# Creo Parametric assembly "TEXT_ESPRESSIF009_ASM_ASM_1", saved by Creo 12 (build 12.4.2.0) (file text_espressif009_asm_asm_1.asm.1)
Units: Custom; MM, KILOGRAM, SECS

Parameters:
  PTC_WM_ITERATION = "0"
  PTC_WM_VERSION = "-.0"
  PTC_WM_LIFECYCLE_STATE = "In Work"
  PTC_WM_LIFECYCLE = "MO_CADDocument"
  PTC_WM_CREATED_BY = "Maximilian Roepper (Z0017RMS: MO)"
  PTC_WM_CREATED_ON = "18-Sep-26 11:36:42 AM"
  PTC_WM_MODIFIED_BY = "Maximilian Roepper (Z0017RMS: MO)"
  PTC_WM_MODIFIED_ON = "18-Sep-26 11:36:46 AM"
  PDMLINKNUMBER = "PDM000071455100"
  PTC_WM_NUMBER = "PDM000071455100"

Other parameters: WEIGHT, WEIGHT_FACTOR, WEIGHT_ADD, MC_ERRORS, SUPPLIER

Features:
  1. coordinate system
  2. imported feature
  3. component "TEXT_ESPRESSIF_PRT_1"
  4. component "TEXT_ESPRESSIF001_PRT_1"
  5. component "TEXT_ESPRESSIF002_PRT_1"
  6. component "TEXT_ESPRESSIF003_PRT_1"
  7. component "TEXT_ESPRESSIF004_PRT_1"
  8. component "TEXT_ESPRESSIF005_PRT_1"
  9. component "TEXT_ESPRESSIF006_PRT_1"
  10. component "TEXT_ESPRESSIF007_PRT_1"
  11. component "TEXT_ESPRESSIF008_PRT_1"

Other named items: DRW_VIEW_ORG, ROUGH-GROB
